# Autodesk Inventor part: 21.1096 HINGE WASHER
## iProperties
Created: 2007-01
Part Number: 21.1096 HINGE WASHER
Material: UHMW, White
Document SubType Name: Modeling
Designer: Andy Moles
Mass: 0.0772419 g
Surface Area: 1.82605 cm^2
Volume: 0.0821723 cm^3
Density: 0.94 g/cm^3
Author: Andy Moles
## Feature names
1. Extrusion1
